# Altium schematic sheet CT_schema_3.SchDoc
size 334 x 183 mm
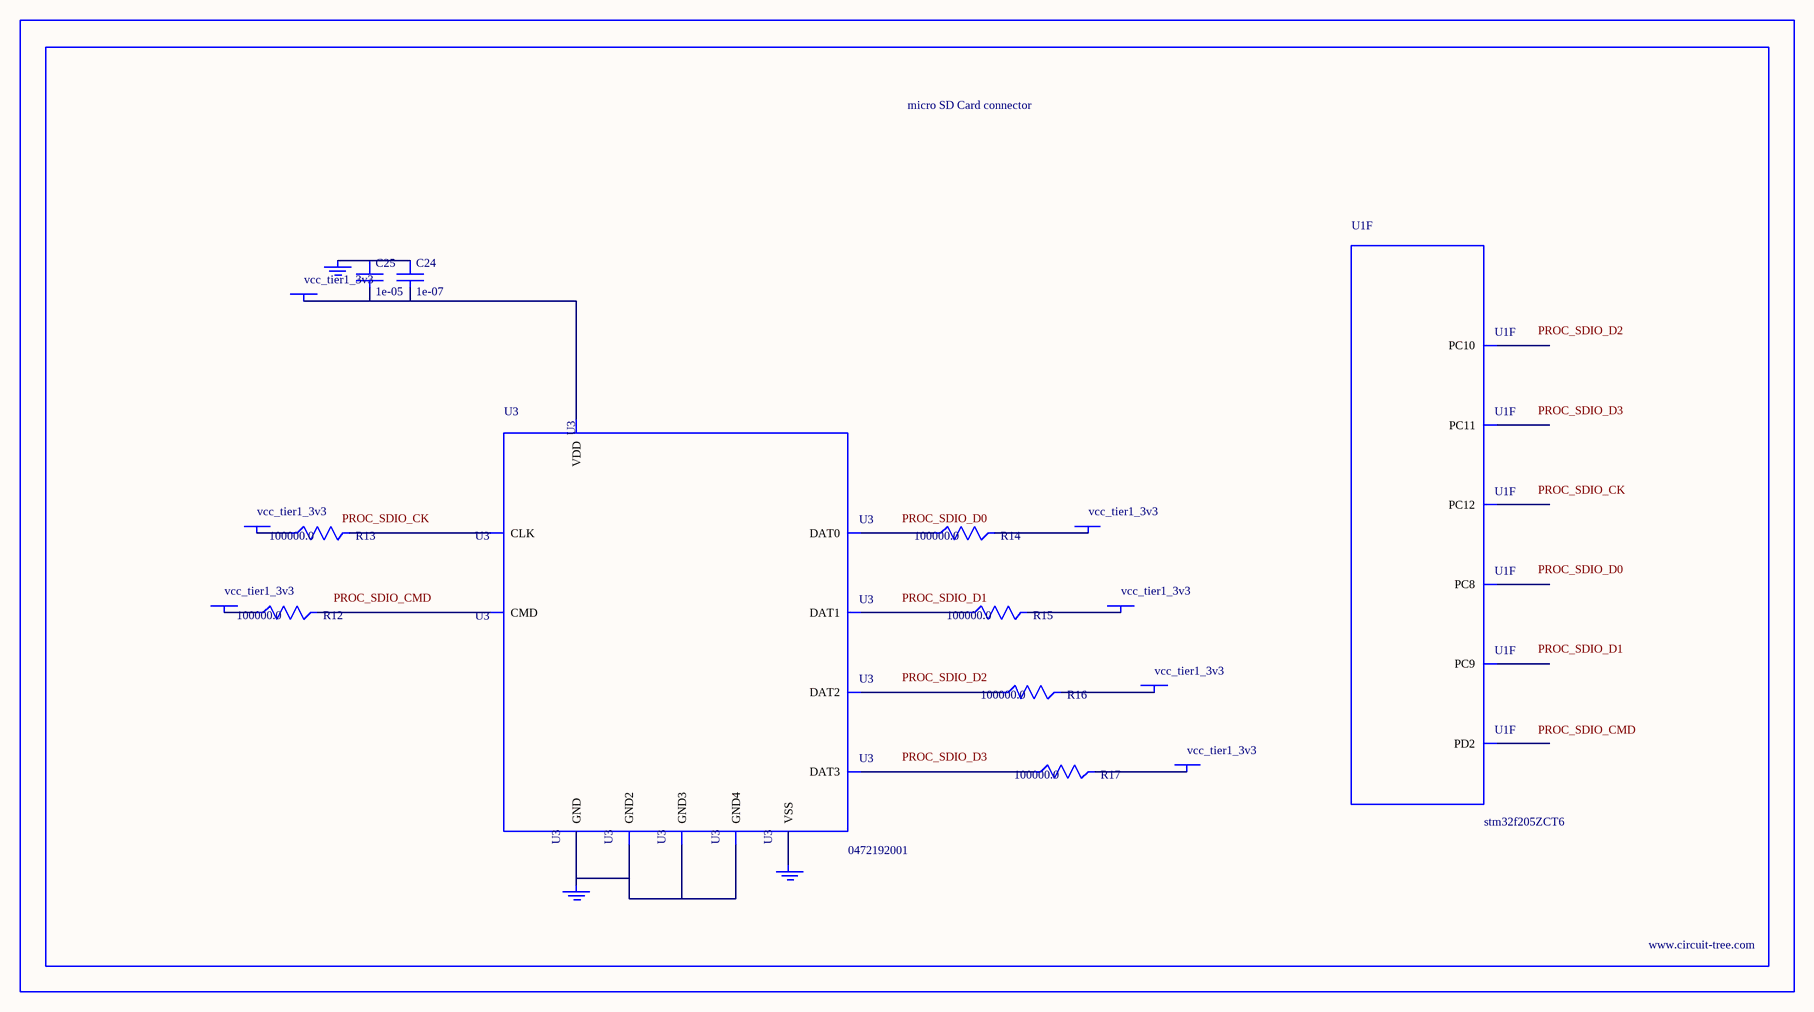
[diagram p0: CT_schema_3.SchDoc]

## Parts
BORDER2  (no value)
C24  1e-07  [C0402]
C25  1e-05  [C0805]
GND_INSTANCE_2_0  (no value)
GND_INSTANCE_2_1  (no value)
GND_INSTANCE_2_2  (no value)
POWER_INSTANCE_2_0  vcc_tier1_3v3
POWER_INSTANCE_2_1  vcc_tier1_3v3
POWER_INSTANCE_2_2  vcc_tier1_3v3
POWER_INSTANCE_2_3  vcc_tier1_3v3
POWER_INSTANCE_2_4  vcc_tier1_3v3
POWER_INSTANCE_2_5  vcc_tier1_3v3
POWER_INSTANCE_2_6  vcc_tier1_3v3
R12  100000.0  [R0603]
R13  100000.0  [R0603]
R14  100000.0  [R0603]
R15  100000.0  [R0603]
R16  100000.0  [R0603]
R17  100000.0  [R0603]
U1  stm32f205ZCT6  [LQFP144]  (part F of 12)
U3  0472192001  [MOLEX_47219-2001]

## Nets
NetC24_1: C24.1 C25.1 GND_INSTANCE_2_0.0(GND)
NetC24_2: C24.2 C25.2 POWER_INSTANCE_2_3.0(PWR) U3.4(VDD)
NetGND_INSTANCE_2_1_0: GND_INSTANCE_2_1.0(GND) U3.6(VSS)
NetGND_INSTANCE_2_2_0: GND_INSTANCE_2_2.0(GND) U3.G1(GND) U3.G2(GND2) U3.G3(GND3) U3.G4(GND4)
NetPOWER_INSTANCE_2_0_0: POWER_INSTANCE_2_0.0(PWR) R16.2
NetPOWER_INSTANCE_2_1_0: POWER_INSTANCE_2_1.0(PWR) R17.2
NetPOWER_INSTANCE_2_2_0: POWER_INSTANCE_2_2.0(PWR) R12.1
NetPOWER_INSTANCE_2_4_0: POWER_INSTANCE_2_4.0(PWR) R13.1
NetPOWER_INSTANCE_2_5_0: POWER_INSTANCE_2_5.0(PWR) R14.2
NetPOWER_INSTANCE_2_6_0: POWER_INSTANCE_2_6.0(PWR) R15.2
NetR12_2: R12.2 U3.3(CMD)
NetR13_2: R13.2 U3.5(CLK)
NetR14_1: R14.1 U3.7(DAT0)
NetR15_1: R15.1 U3.8(DAT1)
NetR16_1: R16.1 U3.1(DAT2)
NetR17_1: R17.1 U3.2(DAT3)

Not connected (* = marked no-connect by the designer): U1 98(PC8) 99(PC9) 111(PC10) 112(PC11) 113(PC12) 116(PD2)

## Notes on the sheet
- Labels drawn without touching a wire or pin: PROC_SDIO_CK, PROC_SDIO_CMD, PROC_SDIO_D0, PROC_SDIO_D1, PROC_SDIO_D2, PROC_SDIO_D3

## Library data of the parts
BORDER2 = BORDER_PAGE2
C24 = C0402C104K3RACTU
C25 = C0805C106K8RACTU
GND_INSTANCE_2_0-GND_INSTANCE_2_2 = GND
POWER_INSTANCE_2_0-POWER_INSTANCE_2_6 = PWR
R12-R17 = RC0603JR-07100KL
